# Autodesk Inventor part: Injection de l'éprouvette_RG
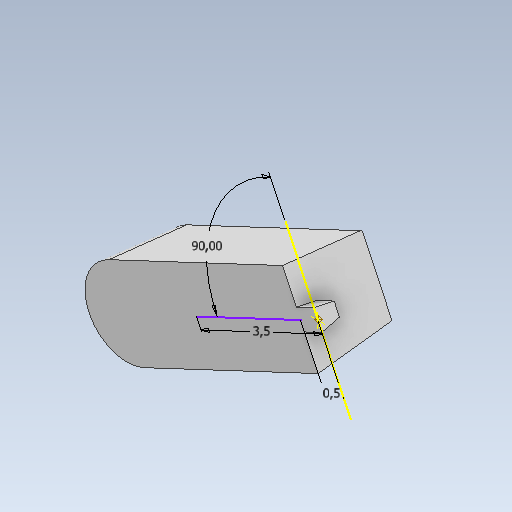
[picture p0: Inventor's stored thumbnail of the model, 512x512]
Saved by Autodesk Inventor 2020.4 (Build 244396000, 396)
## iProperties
Created: 2021-10
Part Number: Injection de l'éprouvette_RG
Material: Générique
Document SubType Name: Modeling
Designer: mel
Density: 1 g/cm^3
Appearance: Par défaut
Author: mel
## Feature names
1. Balayage1
2. Révolution1 [Revolution]
3. Extrusion1
4. Lissage2
## Parameters: d0 = 0, d1 = 3.5 mm, d2 = 90 deg, d3 = 0.5 mm, d4 = 2.18262 mm, d5 = 2 mm, d6 = 85 deg, d7 = 85 deg, d8 = 0.05 mm, d9 = 0, d10 = 0, d11 = 2 mm, d12 = 1.09131 mm, d13 = 2 mm, d14 = 85 deg, d15 = 0.05 mm, d16 = 180 deg, d17 = 2.18262 mm, d18 = 2 mm, d19 = 85 deg, d20 = 85 deg, d21 = 0.05 mm, d22 = 2 mm, d23 = 0, d24 = 0, d25 = 3 mm, d41 = 0.1 mm, d42 = 0.5 mm, d43 = 0.5 mm, d44 = 80 deg, d45 = 80 deg, d46 = 0.5 mm, d47 = 0.5 mm, d48 = 80 deg, d49 = 80 deg, d50 = 0, d51 = 90 deg, d52 = 0, d53 = 90 deg, d54 = 0.1 mm
